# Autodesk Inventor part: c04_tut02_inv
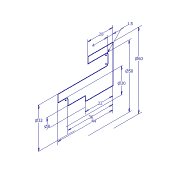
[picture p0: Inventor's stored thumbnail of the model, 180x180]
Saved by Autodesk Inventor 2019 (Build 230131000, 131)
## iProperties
Created: 2017-04
Part Number: c04_tut02_inv
Material: Generic
Document SubType Name: Modeling
Designer: CADCIM 00
Density: 1 g/cm^3
Appearance: Default
Author: CADCIM 00
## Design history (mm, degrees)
sketch "Sketch1"
  geometry: L1 (0, 0)-(-22, 0); L2 (-22, 0)-(-22, 4); L3 (-22, 4)-(-36, 4); L4 (-36, 4)-(-36, 8.5); L5 (-37.5, 10)-(-44, 10); L6 (-44, 10)-(-44, 16); L7 (-44, 16)-(-5.5, 16); L8 (-4, 17.5)-(-4, 23.5); L9 (-5.5, 25)-(-20, 25); L10 (-20, 25)-(-20, 30); L11 (-20, 30)-(0, 30); L12 (0, 30)-(0, 0); A1 r 1.5 centre (-5.5, 23.5) between (-4, 23.5) and (-5.5, 25); A2 r 1.5 centre (-37.5, 8.5) between (-36, 8.5) and (-37.5, 10); A3 r 1.5 centre (-5.5, 17.5) between (-5.5, 16) and (-4, 17.5)
  constraints: 24 end point, 11 perpendicular, 6 point on circle, 6 tangent, 3 centre point, 2 equal radius, 1 horizontal
  dimensions: "d0" = 8 diameter of L3 L1; "d1" = 20 diameter of L5 L1; "d2" = 32 diameter of L7 L1; "d3" = 50 diameter of L9 L1; "d4" = 60 diameter of L11 L1; "d5" = 4 distance between parallel lines of L8 L12; "d6" = 20 distance of L10.end L11.end; "d7" = 22 distance of L1.start L1.end; "d9" = 36 distance between parallel lines of L4 L12; "d10" = 44 distance between parallel lines of L12 L6; "d11" = 1.5 radius of A1
